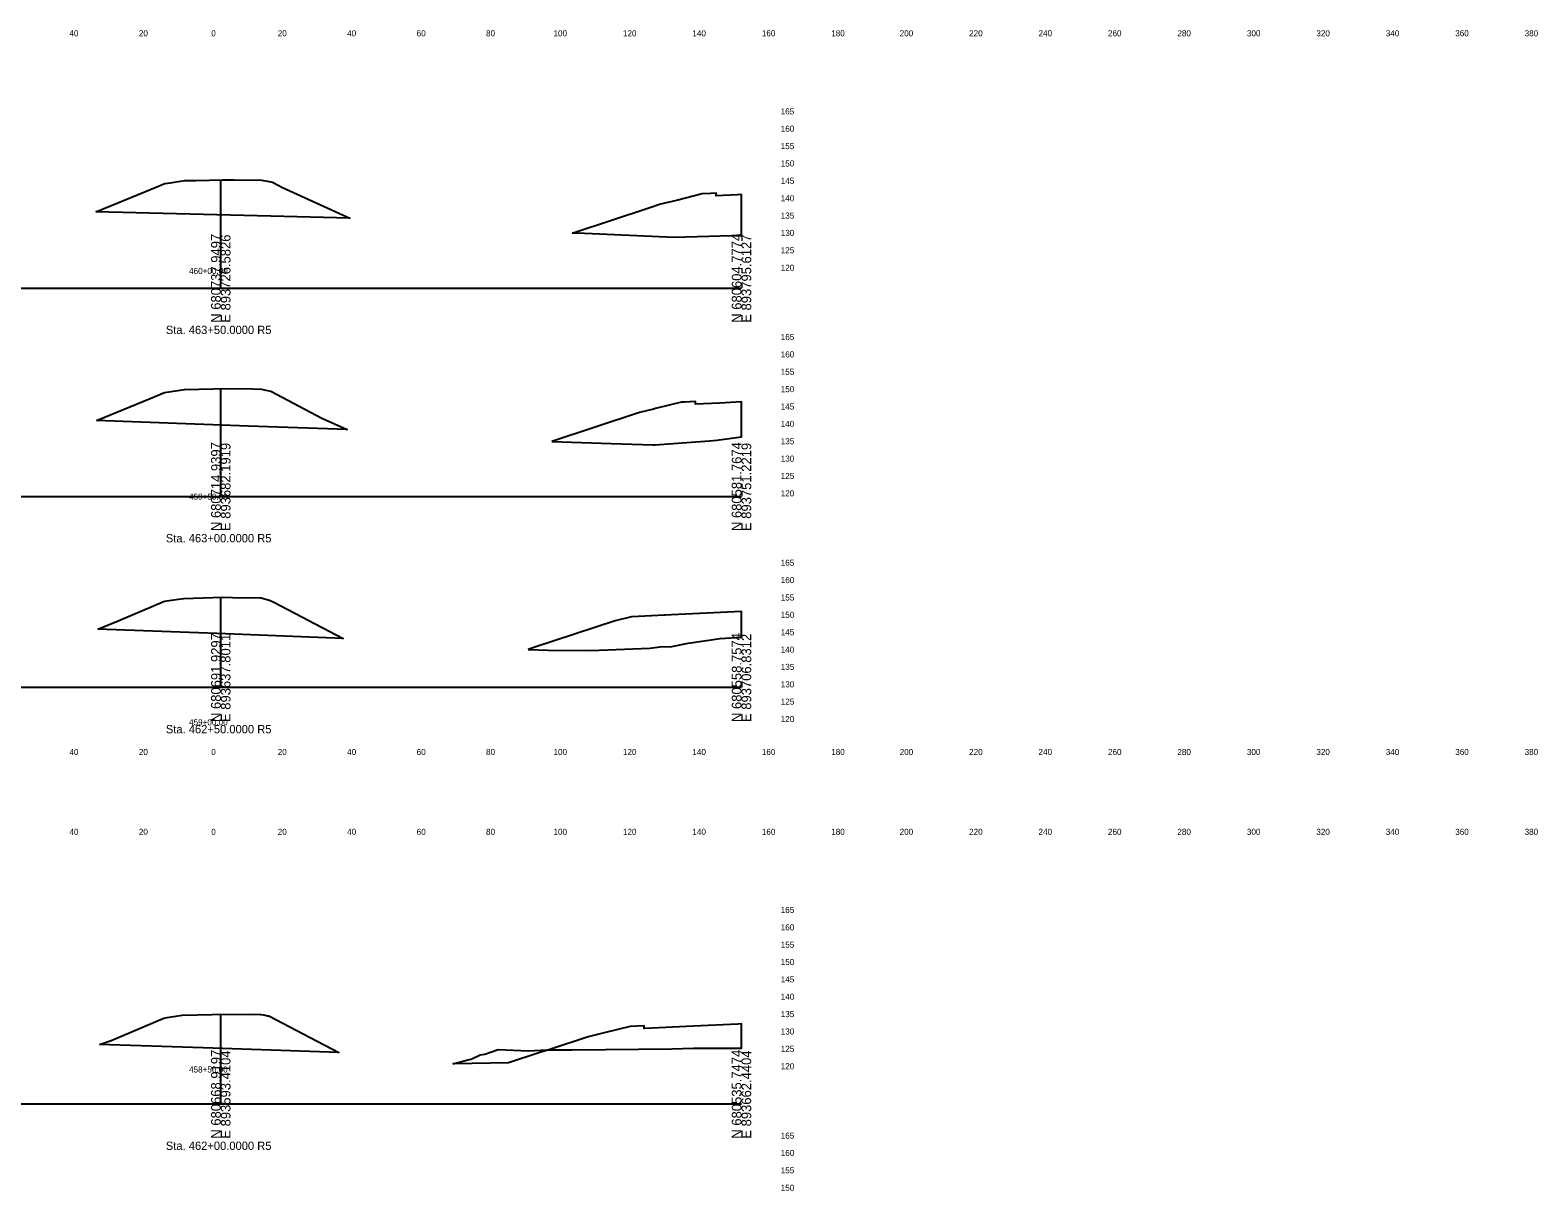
# Model space of a CAD drawing. Extents: x 21059 to 22955, y 6470 to 17494.
# Drawn here: x 21589.9 to 22024.2, y 8189.8 to 8524.1 of the extents above; entities that cross this region are included whole.
import ezdxf

# ---------------------------------------------------------------- set-up
doc = ezdxf.new("R2010")
doc.units = 0
for name, color, linetype in [('CONST_DCH', 7, 'Continuous'), ('Draft_XS_Grid', 7, 'Continuous'), ('Draft_XS_Text', 7, 'Continuous'), ('DTM CONTOURS_MAJOR', 7, 'Continuous'), ('SLOPE_STAKES_FILL', 7, 'Continuous'), ('X_PROFILES_1', 7, 'Continuous'), ('XS_SHEET_EW_TX_VOLUME', 7, 'Continuous')]:
    doc.layers.add(name, color=color, linetype=linetype)

msp = doc.modelspace()

# ---------------------------------------------------------------- linework, layer by layer
at = {"layer": 'DTM CONTOURS_MAJOR'}
for p, q in [((21644.84, 8449.84), (21644.84, 8481.04)), ((21494.84, 8449.84), (21644.84, 8449.84)), ((21644.84, 8449.84), (21794.84, 8449.84)), ((21644.84, 8389.84), (21644.84, 8420.91)), ((21494.84, 8389.84), (21644.84, 8389.84)), ((21644.84, 8389.84), (21794.84, 8389.84)), ((21644.84, 8334.84), (21644.84, 8360.77)), ((21494.84, 8334.84), (21644.84, 8334.84)), ((21644.84, 8334.84), (21794.84, 8334.84)), ((21644.84, 8214.84), (21644.84, 8240.71)), ((21494.84, 8214.84), (21644.84, 8214.84)), ((21644.84, 8214.84), (21794.84, 8214.84))]:
    msp.add_line(p, q, dxfattribs=at)
at = {"layer": 'XS_SHEET_EW_TX_VOLUME'}
for points in [[(21608.89, 8471.79), (21623.14, 8477.61), (21628.74, 8479.91), (21630.27, 8480.15), (21634.43, 8480.77), (21637.63, 8480.83), (21645.38, 8481.04), (21648.69, 8480.99), (21656.56, 8480.87), (21658.82, 8480.49), (21659.73, 8480.31), (21662.65, 8478.77), (21681.99, 8469.93), (21659.3, 8470.51)], [(21746.64, 8465.72), (21747.51, 8465.69), (21775.45, 8464.52), (21792.01, 8464.99), (21794.84, 8465.2), (21794.84, 8476.74), (21793.64, 8476.68), (21787.58, 8476.39), (21787.58, 8476.82), (21787.58, 8477.14), (21785.97, 8477.07), (21783.55, 8476.95), (21776.08, 8475.09), (21771.48, 8473.95), (21768.19, 8472.86)], [(21746.05, 8465.74), (21746.64, 8465.72), (21746.37, 8465.63), (21746.22, 8465.68)], [(21609, 8411.69), (21624.49, 8418.01), (21628.63, 8419.77), (21629.88, 8419.95), (21634.4, 8420.62), (21642.8, 8420.84), (21645.38, 8420.91), (21653.99, 8420.78), (21656.53, 8420.75), (21657.33, 8420.52), (21659.28, 8420.12), (21673.94, 8412.4), (21681.25, 8409.06), (21652.78, 8410.09)], [(21740.21, 8405.62), (21757.29, 8405.08), (21769.29, 8404.71), (21770.02, 8404.7), (21771.24, 8404.75), (21785.58, 8405.82), (21787.69, 8406.06), (21794.84, 8406.99), (21794.84, 8417.03), (21788.46, 8416.72), (21781.57, 8416.4), (21781.57, 8416.63), (21781.57, 8417.15), (21778.47, 8417), (21777.53, 8416.96), (21770.05, 8415.1), (21769.49, 8414.96), (21765.43, 8413.96)], [(21609.44, 8351.61), (21615.32, 8354.01), (21628.61, 8359.64), (21632.63, 8360.24), (21634.16, 8360.46), (21637.01, 8360.54), (21645.29, 8360.77), (21648.25, 8360.72), (21656.51, 8360.65), (21658.46, 8360.07), (21658.86, 8359.98), (21658.87, 8359.98), (21660.1, 8359.34), (21680.13, 8348.91), (21646.27, 8350.2)], [(21733.37, 8345.76), (21739.16, 8345.58), (21751.43, 8345.44), (21768.42, 8346.14), (21772.11, 8346.57), (21774.34, 8346.45), (21779.5, 8347.57), (21788.73, 8348.94), (21794.84, 8349.31), (21794.84, 8356.67), (21788.81, 8356.38), (21778.68, 8355.91), (21774.66, 8355.72), (21772.87, 8355.63), (21772.64, 8355.62), (21768.94, 8355.45), (21763.11, 8355.17), (21758.49, 8354.03), (21735.31, 8346.39)], [(21609.92, 8231.97), (21613.22, 8233.15), (21628.39, 8239.57), (21629.4, 8239.71), (21633.7, 8240.37), (21642.32, 8240.61), (21644.87, 8240.71), (21653.56, 8240.64), (21656.18, 8240.66), (21656.25, 8240.63), (21657.27, 8240.47), (21658.64, 8240.15), (21658.68, 8240.19), (21670.59, 8233.96), (21678.81, 8229.68), (21639.76, 8230.98)], [(21739.32, 8230.46), (21746.09, 8230.39), (21774.76, 8230.67), (21780.98, 8230.88), (21790.91, 8230.86), (21794.84, 8230.89), (21794.84, 8237.91), (21793.82, 8237.86), (21781.03, 8237.27), (21766.95, 8236.61), (21766.85, 8236.6), (21766.85, 8237.35), (21766.85, 8237.35), (21766.83, 8237.35), (21762.79, 8237.16), (21755.26, 8235.31), (21750.63, 8234.17)], [(21711.73, 8226.41), (21716.35, 8227.63), (21716.98, 8227.74), (21719.57, 8229.01), (21720.89, 8229.21), (21724.71, 8230.54), (21733.53, 8230.09), (21738.8, 8230.46), (21739.32, 8230.46), (21736.77, 8229.62), (21727.74, 8226.66), (21717.26, 8226.49)]]:
    msp.add_lwpolyline(points, close=True, dxfattribs=at)

# ---------------------------------------------------------------- texts
at = {"layer": 'CONST_DCH'}
for p in [(21746.33, 8465.57), (21746.33, 8465.57), (21740.17, 8405.56), (21740.17, 8405.56), (21733.33, 8345.7), (21733.33, 8345.7), (21727.7, 8226.6), (21727.7, 8226.6)]:
    msp.add_text('X', height=0.12, dxfattribs=at).set_placement(p)
at = {"layer": 'Draft_XS_Grid'}
for s, p in [('  165  ', (21804.84, 8499.84)), ('  160  ', (21804.84, 8494.84)), ('  155  ', (21804.84, 8489.84)), ('  150  ', (21804.84, 8484.84)), ('  145  ', (21804.84, 8479.84)), ('  140  ', (21804.84, 8474.84)), ('  135  ', (21804.84, 8469.84)), ('  130  ', (21804.84, 8464.84)), ('  125  ', (21804.84, 8459.84)), ('  120  ', (21804.84, 8454.84)), ('  165  ', (21804.84, 8434.84)), ('  160  ', (21804.84, 8429.84)), ('  155  ', (21804.84, 8424.84)), ('  150  ', (21804.84, 8419.84)), ('  145  ', (21804.84, 8414.84)), ('  140  ', (21804.84, 8409.84)), ('  135  ', (21804.84, 8404.84)), ('  130  ', (21804.84, 8399.84)), ('  125  ', (21804.84, 8394.84)), ('  120  ', (21804.84, 8389.84)), ('  165  ', (21804.84, 8369.84)), ('  160  ', (21804.84, 8364.84)), ('  155  ', (21804.84, 8359.84)), ('  150  ', (21804.84, 8354.84)), ('  145  ', (21804.84, 8349.84)), ('  140  ', (21804.84, 8344.84)), ('  135  ', (21804.84, 8339.84)), ('  130  ', (21804.84, 8334.84)), ('  125  ', (21804.84, 8329.84)), ('  120  ', (21804.84, 8324.84)), ('  165  ', (21804.84, 8269.84)), ('  160  ', (21804.84, 8264.84)), ('  155  ', (21804.84, 8259.84)), ('  150  ', (21804.84, 8254.84)), ('  145  ', (21804.84, 8249.84)), ('  140  ', (21804.84, 8244.84)), ('  135  ', (21804.84, 8239.84)), ('  130  ', (21804.84, 8234.84)), ('  125  ', (21804.84, 8229.84)), ('  120  ', (21804.84, 8224.84)), ('  165  ', (21804.84, 8204.84)), ('  160  ', (21804.84, 8199.84)), ('  155  ', (21804.84, 8194.84)), ('  150  ', (21804.84, 8189.84))]:
    msp.add_text(s, height=1.75, dxfattribs=at).set_placement(p)
at = {"layer": 'Draft_XS_Text'}
for s, p in [('  40  ', (21599.95, 8522.34)), ('  20  ', (21619.95, 8522.34)), ('  0  ', (21640.81, 8522.34)), ('  0  ', (21640.81, 8522.34)), ('  20  ', (21659.95, 8522.34)), ('  40  ', (21679.95, 8522.34)), ('  60  ', (21699.97, 8522.34)), ('  80  ', (21719.95, 8522.34)), ('  100  ', (21739.39, 8522.34)), ('  120  ', (21759.39, 8522.34)), ('  140  ', (21779.39, 8522.34)), ('  160  ', (21799.4, 8522.34)), ('  180  ', (21819.39, 8522.34)), ('  200  ', (21839.1, 8522.34)), ('  220  ', (21859.1, 8522.34)), ('  240  ', (21879.1, 8522.34)), ('  260  ', (21899.11, 8522.34)), ('  280  ', (21919.1, 8522.34)), ('  300  ', (21939.13, 8522.34)), ('  320  ', (21959.13, 8522.34)), ('  340  ', (21979.13, 8522.34)), ('  360  ', (21999.14, 8522.34)), ('  380  ', (22019.13, 8522.34)), ('  40  ', (21599.95, 8315.34)), ('  20  ', (21619.95, 8315.34)), ('  0  ', (21640.81, 8315.34)), ('  0  ', (21640.81, 8315.34)), ('  20  ', (21659.95, 8315.34)), ('  40  ', (21679.95, 8315.34)), ('  60  ', (21699.97, 8315.34)), ('  80  ', (21719.95, 8315.34)), ('  100  ', (21739.39, 8315.34)), ('  120  ', (21759.39, 8315.34)), ('  140  ', (21779.39, 8315.34)), ('  160  ', (21799.4, 8315.34)), ('  180  ', (21819.39, 8315.34)), ('  200  ', (21839.1, 8315.34)), ('  220  ', (21859.1, 8315.34)), ('  240  ', (21879.1, 8315.34)), ('  260  ', (21899.11, 8315.34)), ('  280  ', (21919.1, 8315.34)), ('  300  ', (21939.13, 8315.34)), ('  320  ', (21959.13, 8315.34)), ('  340  ', (21979.13, 8315.34)), ('  360  ', (21999.14, 8315.34)), ('  380  ', (22019.13, 8315.34)), ('  40  ', (21599.95, 8292.34)), ('  20  ', (21619.95, 8292.34)), ('  0  ', (21640.81, 8292.34)), ('  0  ', (21640.81, 8292.34)), ('  20  ', (21659.95, 8292.34)), ('  40  ', (21679.95, 8292.34)), ('  60  ', (21699.97, 8292.34)), ('  80  ', (21719.95, 8292.34)), ('  100  ', (21739.39, 8292.34)), ('  120  ', (21759.39, 8292.34)), ('  140  ', (21779.39, 8292.34)), ('  160  ', (21799.4, 8292.34)), ('  180  ', (21819.39, 8292.34)), ('  200  ', (21839.1, 8292.34)), ('  220  ', (21859.1, 8292.34)), ('  240  ', (21879.1, 8292.34)), ('  260  ', (21899.11, 8292.34)), ('  280  ', (21919.1, 8292.34)), ('  300  ', (21939.13, 8292.34)), ('  320  ', (21959.13, 8292.34)), ('  340  ', (21979.13, 8292.34)), ('  360  ', (21999.14, 8292.34)), ('  380  ', (22019.13, 8292.34))]:
    msp.add_text(s, height=1.75, dxfattribs=at).set_placement(p)
at = {"layer": 'DTM CONTOURS_MAJOR'}
for s, p in [('N 680737.9497', (21644.84, 8439.84)), ('E 893726.5826', (21647.64, 8439.84)), ('N 680604.7774', (21794.84, 8439.84)), ('E 893795.6127', (21797.64, 8439.84)), ('N 680714.9397', (21644.84, 8379.84)), ('E 893682.1919', (21647.64, 8379.84)), ('N 680581.7674', (21794.84, 8379.84)), ('E 893751.2219', (21797.64, 8379.84)), ('N 680691.9297', (21644.84, 8324.84)), ('E 893637.8011', (21647.64, 8324.84)), ('N 680558.7574', (21794.84, 8324.84)), ('E 893706.8312', (21797.64, 8324.84)), ('N 680668.9197', (21644.84, 8204.84)), ('N 680535.7474', (21794.84, 8204.84)), ('E 893593.4104', (21647.64, 8204.84)), ('E 893662.4404', (21797.64, 8204.84))]:
    msp.add_text(s, height=2.8, rotation=90, dxfattribs=at).set_placement(p)
at = {"layer": 'SLOPE_STAKES_FILL'}
for s, p in [('  460+00.00  ', (21634.41, 8453.89)), ('  459+50.00  ', (21634.4, 8388.89)), ('  459+00.00  ', (21634.4, 8323.89)), ('  458+50.00  ', (21634.4, 8223.89))]:
    msp.add_text(s, height=1.75, dxfattribs=at).set_placement(p)
at = {"layer": 'X_PROFILES_1'}
for s, p in [('Sta. 463+50.0000 R5', (21629.02, 8436.59)), ('Sta. 463+00.0000 R5', (21629.02, 8376.59)), ('Sta. 462+50.0000 R5', (21629.02, 8321.59)), ('Sta. 462+00.0000 R5', (21629.02, 8201.59))]:
    msp.add_text(s, height=2.4, dxfattribs=at).set_placement(p)

doc.saveas('drawing.dxf')
